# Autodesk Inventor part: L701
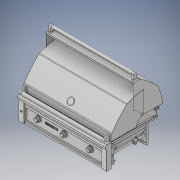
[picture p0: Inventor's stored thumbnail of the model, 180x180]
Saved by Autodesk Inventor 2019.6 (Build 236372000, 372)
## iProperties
Created: 2025-04
Part Number: L701
Material: Generic
Description: CATIA V5 STEP
Document SubType Name: Modeling
Designer: MMAK
Authority: none
Density: 1 g/cm^3
Appearance: Default
Company: none
Title: C:\Users\MMAK\Documents\SmarTeam\WEBSITE CAD\SEDONA\2025 SEDONA\L701.stp
Author: none
Revision Number: ANY
Sending System: CATIA V5 STEP AP203 v2
Preprocessor: CATIA Unofficial Packaging Version SP2
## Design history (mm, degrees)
feature "80780-1_34565-2-solid1"
feature "80780-1_34563-2-solid1"
feature "80780-1_34564-2-solid1"
feature "80780-1_31643-1-solid1"
feature "80780-1_31643-2-solid1"
feature "80780-1_30616-3-solid1"
feature "80780-1_30616-4-solid1"
feature "80780-1_30616-5-solid1"
feature "80780-1_30616-6-solid1"
feature "80780-1_30616-9-solid1"
feature "80780-1_30616-10-solid1"
feature "80780-1_30616-11-solid1"
feature "80780-1_30616-12-solid1"
feature "80780-1_33759-1-solid1"
feature "80780-1_33758-1-solid1"
feature "80780-1_30292-1-solid1"
feature "80780-1_30292-2-solid1"
feature "80780-1_14011-1-solid1"
feature "80780-1_14011-2-solid1"
feature "80780-1_14011-3-solid1"
feature "80780-1_14011-4-solid1"
feature "80780-1_14011-5-solid1"
feature "80780-1_14011-6-solid1"
feature "80780-1_30616-16-solid1"
feature "80780-1_30616-17-solid1"
feature "80780-1_30616-13-solid1"
feature "80780-1_30616-14-solid1"
feature "80780-1_30616-15-solid1"
feature "80780-1_34566-3-solid1"
feature "80780-1_14034-1-solid1"
feature "80780-1_14034-2-solid1"
feature "80780-1_14034-3-solid1"
feature "80780-1_14034-4-solid1"
feature "80780-1_14034-5-solid1"
feature "80780-1_14011-7-solid1"
feature "80780-1_14011-8-solid1"
feature "80780-1_14011-9-solid1"
feature "80780-1_14011-11-solid1"
feature "80780-1_14011-12-solid1"
feature "80780-1_14011-14-solid1"
feature "80780-1_14011-15-solid1"
feature "80780-1_14011-17-solid1"
feature "80780-1_14011-18-solid1"
feature "80780-1_14011-20-solid1"
feature "80780-1_14011-22-solid1"
feature "80780-1_14011-24-solid1"
feature "80780-1_14011-26-solid1"
feature "80780-1_14011-28-solid1"
feature "80780-1_14011-31-solid1"
feature "80780-1_14011-35-solid1"
feature "80780-1_14011-37-solid1"
feature "80780-1_14011-39-solid1"
feature "80780-1_14011-41-solid1"
feature "80780-1_32620-1-solid1"
feature "80780-1_32620-2-solid1"
feature "80780-1_32620-3-solid1"
feature "80780-1_32620-4-solid1"
feature "80780-1_32620-5-solid1"
feature "80780-1_32620-6-solid1"
feature "80780-1_14011-43-solid1"
feature "80780-1_14011-45-solid1"
feature "70835-1_33767-1-solid1"
feature "70835-1_33768-1-solid1"
feature "70835-1_34572-1-solid1"
feature "70835-2_33767-1-solid1"
feature "70835-2_33768-1-solid1"
feature "70835-2_34572-1-solid1"
feature "81797-1_70833-1_L18041-1-solid1"
feature "81797-1_70833-1_33763-1-solid1"
feature "81797-1_70833-1_37975-1-solid1"
feature "81797-1_32218-1-solid1"
feature "81797-1_32218-2-solid1"
feature "81705-1_70816-1_37995-1-solid1"
feature "81705-1_70816-1_14011-1-solid1"
feature "81705-1_81628-1_37837-2-solid1"
feature "81705-1_81628-1_32218-3-solid1"
feature "81705-1_81628-1_32218-4-solid1"
feature "81705-1_81628-1_31782-1-solid1"
feature "81705-1_81628-1_32769-1-solid1"
feature "81705-1_81628-1_32769-2-solid1"
feature "81705-1_81628-1_32769-3-solid1"
feature "81705-1_81628-1_32769-4-solid1"
feature "81705-1_81627-1_37834-2-solid1"
feature "81705-1_81627-1_32769-1-solid1"
feature "81705-1_81627-1_32769-2-solid1"
feature "81705-1_81627-1_32769-3-solid1"
feature "81705-1_81627-1_32769-4-solid1"
feature "81705-1_81627-1_32769-5-solid1"
feature "81705-1_81627-1_31782-1-solid1"
feature "81705-1_81627-1_32218-3-solid1"
feature "81705-1_81627-1_32218-4-solid1"
feature "81705-1_37845-1-solid1"
feature "81705-1_37846-1-solid1"
feature "81705-1_32470-1-solid1"
feature "81705-1_32470-2-solid1"
feature "81705-1_14012-1-solid1"
feature "81705-1_14012-2-solid1"
feature "81705-1_14012-4-solid1"
feature "81705-1_14012-6-solid1"
feature "81705-1_14012-8-solid1"
feature "81705-1_14012-10-solid1"
feature "81705-1_14012-12-solid1"
feature "81705-1_14012-14-solid1"
feature "81705-1_14014-1-solid1"
feature "81705-1_14014-2-solid1"
feature "81705-1_14014-4-solid1"
feature "81705-1_14014-6-solid1"
feature "38164-1-solid1"
feature "80787-1_80785-1_34603-1-solid1"
feature "80787-1_80785-1_34603-1-solid2"
feature "80787-1_80785-1_L10041-1-solid1"
feature "80787-1_80785-1_L10041-2-solid1"
feature "80787-1_13029-1-solid1"
feature "80787-1_34267-1-solid1"
feature "80787-1_34268-1-solid1"
feature "80787-1_13024-1-solid1"
feature "NONE"
feature "NONE:1"
feature "NONE:2"
feature "80787-1_13024-2-solid1"
feature "33558-1-solid1"
feature "10001-1-solid1"
feature "10001-2-solid1"
feature "10001-3-solid1"
feature "31773-1-solid1"
feature "31773-2-solid1"
feature "31773-3-solid1"
feature "81630-1_32106-1-solid1"
feature "81630-1_Part2^81630-1-solid1"
feature "81630-1_Part2^81630-1-solid2"
feature "11117-1-solid1"
feature "11117-2-solid1"
feature "11117-3-solid1"
feature "11117-4-solid1"
feature "L20016-1-solid1"
feature "L20016-2-solid1"
feature "L20016-3-solid1"
feature "L20016-4-solid1"
feature "34605-1-solid1"
feature "34605-2-solid1"
feature "30417-1-solid1"
feature "34106-1-solid1"
feature "14013-1-solid1"
feature "14013-2-solid1"
feature "36967-1-solid1"
feature "36967-2-solid1"
feature "14012-1-solid1"
feature "14012-2-solid1"
feature "14012-3-solid1"
feature "14012-4-solid1"
feature "14012-5-solid1"
feature "32477-1-solid1"
feature "32477-2-solid1"
feature "38157-1-solid1"
feature "38158-1-solid1"
feature "31930-1-solid1"
feature "31930-3-solid1"
feature "31930-4-solid1"
feature "31930-5-solid1"
feature "31930-6-solid1"
feature "31930-7-solid1"
feature "31930-8-solid1"
feature "31930-9-solid1"
feature "31930-10-solid1"
feature "32554-1-solid1"
feature "32554-1-solid2"
feature "32554-2-solid1"
feature "32554-2-solid2"
feature "32554-3-solid1"
feature "32554-3-solid2"
body "Solid1"
body "Solid2"
body "Solid3"
body "Solid4"
body "Solid5"
body "Solid6"
body "Solid7"
body "Solid8"
body "Solid9"
body "Solid10"
body "Solid11"
body "Solid12"
body "Solid13"
body "Solid14"
body "Solid15"
body "Solid16"
body "Solid17"
body "Solid18"
body "Solid19"
body "Solid20"
body "Solid21"
body "Solid22"
body "Solid23"
body "Solid24"
body "Solid25"
body "Solid26"
body "Solid27"
body "Solid28"
body "Solid29"
body "Solid30"
body "Solid31"
body "Solid32"
body "Solid33"
body "Solid34"
body "Solid35"
body "Solid36"
body "Solid37"
body "Solid38"
body "Solid39"
body "Solid40"
body "Solid41"
body "Solid42"
body "Solid43"
body "Solid44"
body "Solid45"
body "Solid46"
body "Solid47"
body "Solid48"
body "Solid49"
body "Solid50"
body "Solid51"
body "Solid52"
body "Solid53"
body "Solid54"
body "Solid55"
body "Solid56"
body "Solid57"
body "Solid58"
body "Solid59"
body "Solid60"
body "Solid61"
body "Solid62"
body "Solid63"
body "Solid64"
body "Solid65"
body "Solid66"
body "Solid67"
body "Solid68"
body "Solid69"
body "Solid70"
body "Solid71"
body "Solid72"
body "Solid73"
body "Solid74"
body "Solid75"
body "Solid76"
body "Solid77"
body "Solid78"
body "Solid79"
body "Solid80"
body "Solid81"
body "Solid82"
body "Solid83"
body "Solid84"
body "Solid85"
body "Solid86"
body "Solid87"
body "Solid88"
body "Solid89"
body "Solid90"
body "Solid91"
body "Solid92"
body "Solid93"
body "Solid94"
body "Solid95"
body "Solid96"
body "Solid97"
body "Solid98"
body "Solid99"
body "Solid100"
body "Solid101"
body "Solid102"
body "Solid103"
body "Solid104"
body "Solid105"
body "Solid106"
body "Solid107"
body "Solid108"
body "Solid109"
body "Solid110"
body "Solid111"
body "Solid112"
body "Solid113"
body "Solid114"
body "Solid115"
body "Solid116"
body "Solid117"
body "Solid118"
body "Solid119"
body "Solid120"
body "Solid121"
body "Solid122"
body "Solid123"
body "Solid124"
body "Solid125"
body "Solid126"
body "Solid127"
body "Solid128"
body "Solid129"
body "Solid130"
body "Solid131"
body "Solid132"
body "Solid133"
body "Solid134"
body "Solid135"
body "Solid136"
body "Solid137"
body "Solid138"
body "Solid139"
body "Solid140"
body "Solid141"
body "Solid142"
body "Solid143"
body "Solid144"
body "Solid145"
body "Solid146"
body "Solid147"
body "Solid148"
body "Solid149"
body "Solid150"
body "Solid151"
body "Solid152"
body "Solid153"
body "Solid154"
body "Solid155"
body "Solid156"
body "Solid157"
body "Solid158"
body "Solid159"
body "Solid160"
body "Solid161"
body "Solid162"
body "Solid163"
body "Solid164"
body "Solid165"
body "Solid166"
body "Solid167"
body "Solid168"
body "Solid169"
body "Solid170"
body "Solid171"
body "Solid172"
body "Solid173"
body "Solid174"
body "Solid175"
body "Solid176"
body "Solid177"
body "Solid178"
body "Solid179"
body "Solid180"
body "Solid181"
body "Solid182"
